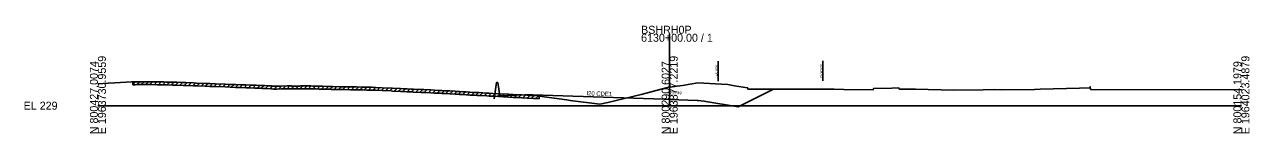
# Model space of a CAD drawing. Extents: x -26 to 1986619, y -10 to 827846.
# Drawn here: x -25.7 to 402.8, y 9990.3 to 10028 of the extents above; entities that cross this region are included whole.
import ezdxf

# ---------------------------------------------------------------- set-up
doc = ezdxf.new("R2010")
doc.units = 0
for name, color, linetype in [('Default', 7, 'Continuous'), ('RD_EX_Road', 7, 'Continuous'), ('RD_PD_ALT2_TrvlWay', 7, 'Continuous'), ('RD_PD_ALT5_LnLine', 7, 'Continuous'), ('RD_PD_ALT5_TrvlWay', 7, 'Continuous'), ('RD_PD_PaveDit', 7, 'Continuous'), ('RD_Sketch2', 7, 'Continuous'), ('RD_XS_ExRW', 7, 'Continuous'), ('RD_XS_NewRW', 7, 'Continuous')]:
    doc.layers.add(name, color=color, linetype=linetype)

msp = doc.modelspace()

# ---------------------------------------------------------------- linework, layer by layer
at = {"layer": 'RD_EX_Road'}
for p, q in [((200, 10000), (200, 10025.2)), ((0, 10000), (200, 10000)), ((200, 10000), (400, 10000))]:
    msp.add_line(p, q, dxfattribs=at)
at = {"layer": 'RD_PD_ALT5_LnLine'}
msp.add_lwpolyline([(0, 10007.66), (3.56, 10007.87), (5.92, 10007.99), (11.81, 10008.3), (12.98, 10008.31), (13.54, 10008.39), (14.2, 10008.4), (15.12, 10008.4), (16.27, 10008.4), (17.1, 10008.39), (17.91, 10008.38), (18.77, 10008.37), (20.83, 10008.33), (22.06, 10008.31), (23.09, 10008.31), (23.91, 10008.29), (26.11, 10008.24), (27.63, 10008.19), (29.76, 10008.11), (30.72, 10008.08), (33.41, 10007.97), (34.44, 10007.93), (37.54, 10007.82), (39.17, 10007.76), (40.78, 10007.7), (41.09, 10007.69), (44.5, 10007.55), (46.23, 10007.47), (48.15, 10007.41), (49.83, 10007.35), (51.76, 10007.29), (53.31, 10007.23), (54.93, 10007.16), (55.4, 10007.14), (56.82, 10007.09), (57.4, 10007.07), (58.21, 10007.05), (59.05, 10007), (60.61, 10006.91), (60.92, 10006.86), (61.42, 10006.84), (62.15, 10006.82), (62.6, 10006.82), (64.06, 10006.85), (66.19, 10006.93), (66.88, 10006.95), (67.6, 10006.9), (67.79, 10006.89), (68.7, 10006.87), (69.54, 10006.86), (70.49, 10006.85), (70.82, 10006.92), (71.13, 10006.92), (72.08, 10006.93), (72.94, 10006.94), (74, 10006.91), (74.47, 10006.9), (75.17, 10006.88), (76.31, 10006.85), (77.41, 10006.83), (78.05, 10006.81), (78.56, 10006.8), (81.06, 10006.74), (81.6, 10006.72), (82.07, 10006.71), (84.73, 10006.64), (85.58, 10006.63), (88.39, 10006.59), (89.1, 10006.58), (90.45, 10006.55), (92.05, 10006.52), (92.6, 10006.51), (93.96, 10006.48), (95.9, 10006.43), (97.2, 10006.38), (99.44, 10006.29), (102.52, 10006.16), (103.09, 10006.13), (105.85, 10006), (106.74, 10005.95), (108.12, 10005.88), (109.62, 10005.81), (110.03, 10005.8), (110.41, 10005.78), (113.1, 10005.66), (114.05, 10005.62), (116.45, 10005.5), (117.71, 10005.44), (119.27, 10005.36), (119.87, 10005.33), (120.26, 10005.31), (121.36, 10005.25), (123.06, 10005.15), (125.02, 10005.04), (125.72, 10005.01), (126.46, 10004.96), (127.65, 10004.88), (128.76, 10004.82), (130.07, 10004.74), (131.82, 10004.65), (132.69, 10004.61), (133.33, 10004.57), (136.05, 10004.42), (136.83, 10004.38), (138.19, 10004.31), (140.12, 10004.21), (143.64, 10003.99), (145.31, 10003.91), (147.14, 10003.81), (148.26, 10003.75), (150.1, 10003.65), (150.69, 10003.62), (152.34, 10003.54), (153.05, 10003.54), (153.64, 10003.54), (154.37, 10003.38), (164.04, 10002.01), (165.18, 10001.87), (175.57, 10000.54), (178.42, 10001.1), (189.98, 10003.92), (199.3, 10006.4), (200, 10006.49), (204.48, 10007.06), (209.89, 10008.02), (218.15, 10007.52), (220.32, 10007.4), (222.69, 10006.9), (227.24, 10006.27), (227.34, 10005.82), (234.38, 10005.8), (244.04, 10005.75), (251.21, 10005.79), (257.55, 10005.76), (260.88, 10005.69), (271.2, 10005.56), (271.3, 10006.01), (277.76, 10006.17), (280.2, 10006.24), (280.3, 10005.79), (285.99, 10005.74), (299.38, 10005.47), (309.62, 10005.58), (313.49, 10005.62), (316.18, 10005.56), (327.63, 10005.68), (329.61, 10005.74), (343.38, 10006.19), (346.96, 10006.25), (347.06, 10006.7), (347.26, 10005.69), (400, 10005.58)], dxfattribs=at)
at = {"layer": 'RD_PD_PaveDit'}
for p, q in [((12.15, 10007.3), (13.18, 10008.34)), ((12.15, 10007.3), (12.15, 10008.3)), ((12.15, 10007.3), (12.98, 10007.31)), ((12.98, 10007.31), (13.54, 10007.39)), ((13.54, 10007.39), (14.2, 10007.4)), ((13.65, 10007.39), (14.66, 10008.4)), ((14.2, 10007.4), (15.12, 10007.4)), ((15.12, 10007.4), (16.27, 10007.4)), ((15.15, 10007.4), (16.14, 10008.4)), ((16.27, 10007.4), (17.1, 10007.39)), ((16.65, 10007.39), (17.64, 10008.38)), ((17.1, 10007.39), (17.91, 10007.38)), ((17.91, 10007.38), (18.77, 10007.37)), ((18.15, 10007.38), (19.13, 10008.36)), ((18.77, 10007.37), (20.83, 10007.33)), ((19.65, 10007.35), (20.63, 10008.33)), ((20.83, 10007.33), (22.06, 10007.31)), ((21.15, 10007.33), (22.13, 10008.31)), ((22.06, 10007.31), (23.09, 10007.31)), ((22.65, 10007.31), (23.63, 10008.3)), ((23.09, 10007.31), (23.91, 10007.29)), ((23.91, 10007.29), (26.11, 10007.24)), ((24.15, 10007.29), (25.12, 10008.26)), ((25.65, 10007.25), (26.62, 10008.22)), ((26.11, 10007.24), (27.63, 10007.19)), ((27.15, 10007.2), (28.11, 10008.17)), ((27.63, 10007.19), (29.76, 10007.11)), ((28.65, 10007.15), (29.61, 10008.12)), ((29.76, 10007.11), (30.72, 10007.08)), ((30.15, 10007.1), (31.11, 10008.06)), ((30.72, 10007.08), (33.41, 10006.97)), ((31.65, 10007.04), (32.61, 10008)), ((33.15, 10006.98), (34.11, 10007.94)), ((33.41, 10006.97), (34.44, 10006.93)), ((34.44, 10006.93), (37.54, 10006.82)), ((34.65, 10006.92), (35.61, 10007.89)), ((36.15, 10006.87), (37.11, 10007.84)), ((37.54, 10006.82), (39.17, 10006.76)), ((37.65, 10006.82), (38.61, 10007.78)), ((39.15, 10006.76), (40.11, 10007.73)), ((39.17, 10006.76), (40.78, 10006.7)), ((40.65, 10006.71), (41.61, 10007.67)), ((40.78, 10006.7), (41.09, 10006.69)), ((41.09, 10006.69), (44.5, 10006.55)), ((42.15, 10006.65), (43.11, 10007.61)), ((43.65, 10006.58), (44.61, 10007.54)), ((44.5, 10006.55), (46.23, 10006.47)), ((45.15, 10006.52), (46.1, 10007.48)), ((46.23, 10006.47), (48.15, 10006.41)), ((46.65, 10006.46), (47.62, 10007.43)), ((48.15, 10006.41), (49.11, 10007.38)), ((48.15, 10006.41), (49.83, 10006.35)), ((49.65, 10006.36), (50.61, 10007.33)), ((49.83, 10006.35), (51.76, 10006.29)), ((51.15, 10006.31), (52.11, 10007.27)), ((51.76, 10006.29), (53.31, 10006.23)), ((52.65, 10006.25), (53.61, 10007.21)), ((54.15, 10006.19), (55.11, 10007.15)), ((55.65, 10006.13), (56.61, 10007.1)), ((57.15, 10006.08), (58.11, 10007.05)), ((58.65, 10006.02), (59.59, 10006.97)), ((60.15, 10005.93), (61.07, 10006.86)), ((61.65, 10005.83), (62.64, 10006.82)), ((63.15, 10005.83), (64.17, 10006.85)), ((64.65, 10005.87), (65.69, 10006.91)), ((66.15, 10005.93), (67.16, 10006.94)), ((67.65, 10005.9), (68.62, 10006.87)), ((69.15, 10005.86), (70.14, 10006.85)), ((70.65, 10005.88), (71.69, 10006.92)), ((72.15, 10005.93), (73.15, 10006.93)), ((73.65, 10005.92), (74.62, 10006.9)), ((75.15, 10005.88), (76.12, 10006.86)), ((76.65, 10005.84), (77.63, 10006.82)), ((78.15, 10005.81), (79.12, 10006.79)), ((79.65, 10005.77), (80.62, 10006.75)), ((81.15, 10005.73), (82.12, 10006.71)), ((82.65, 10005.7), (83.62, 10006.67)), ((84.15, 10005.66), (85.12, 10006.64)), ((85.65, 10005.63), (86.63, 10006.61)), ((87.15, 10005.61), (88.13, 10006.59)), ((88.65, 10005.59), (89.63, 10006.57)), ((90.15, 10005.56), (91.13, 10006.54)), ((91.65, 10005.53), (92.63, 10006.51)), ((93.15, 10005.5), (94.13, 10006.48)), ((94.65, 10005.46), (95.62, 10006.44)), ((96.15, 10005.42), (97.11, 10006.38)), ((97.65, 10005.36), (98.61, 10006.33)), ((99.15, 10005.3), (100.11, 10006.26)), ((53.31, 10006.23), (54.93, 10006.16)), ((54.93, 10006.16), (55.4, 10006.14)), ((55.4, 10006.14), (56.82, 10006.09)), ((56.82, 10006.09), (57.4, 10006.07)), ((57.4, 10006.07), (58.21, 10006.05)), ((58.21, 10006.05), (59.05, 10006)), ((59.05, 10006), (60.61, 10005.91)), ((60.61, 10005.91), (60.92, 10005.86)), ((60.92, 10005.86), (61.42, 10005.84)), ((61.42, 10005.84), (62.15, 10005.82)), ((62.15, 10005.82), (62.6, 10005.82)), ((62.6, 10005.82), (64.06, 10005.85)), ((64.06, 10005.85), (66.19, 10005.93)), ((66.19, 10005.93), (66.88, 10005.95)), ((66.88, 10005.95), (67.6, 10005.9)), ((67.6, 10005.9), (67.79, 10005.89)), ((67.79, 10005.89), (68.7, 10005.87)), ((68.7, 10005.87), (69.54, 10005.86)), ((69.54, 10005.86), (70.49, 10005.85)), ((70.49, 10005.85), (70.82, 10005.92)), ((70.82, 10005.92), (71.13, 10005.92)), ((71.13, 10005.92), (72.08, 10005.93)), ((72.08, 10005.93), (72.94, 10005.94)), ((72.94, 10005.94), (74, 10005.91)), ((74, 10005.91), (74.47, 10005.9)), ((74.47, 10005.9), (75.17, 10005.88)), ((75.17, 10005.88), (76.31, 10005.85)), ((76.31, 10005.85), (77.41, 10005.83)), ((77.41, 10005.83), (78.05, 10005.81)), ((78.05, 10005.81), (78.56, 10005.8)), ((78.56, 10005.8), (81.06, 10005.74)), ((81.06, 10005.74), (81.6, 10005.72)), ((81.6, 10005.72), (82.07, 10005.71)), ((82.07, 10005.71), (84.73, 10005.64)), ((84.73, 10005.64), (85.58, 10005.63)), ((85.58, 10005.63), (88.39, 10005.59)), ((88.39, 10005.59), (89.1, 10005.58)), ((89.1, 10005.58), (90.45, 10005.55)), ((90.45, 10005.55), (92.05, 10005.52)), ((92.05, 10005.52), (92.6, 10005.51)), ((92.6, 10005.51), (93.96, 10005.48)), ((93.96, 10005.48), (95.9, 10005.43)), ((95.9, 10005.43), (97.2, 10005.38)), ((97.2, 10005.38), (99.44, 10005.29)), ((99.44, 10005.29), (102.52, 10005.16)), ((100.65, 10005.24), (101.6, 10006.2)), ((102.15, 10005.18), (103.1, 10006.13)), ((102.52, 10005.16), (103.09, 10005.13)), ((103.09, 10005.13), (105.85, 10005)), ((103.65, 10005.11), (104.6, 10006.06)), ((105.15, 10005.03), (106.1, 10005.99)), ((105.85, 10005), (106.74, 10004.95)), ((106.65, 10004.96), (107.59, 10005.9)), ((106.74, 10004.95), (108.12, 10004.88)), ((108.12, 10004.88), (109.62, 10004.81)), ((108.15, 10004.87), (109.11, 10005.84)), ((109.62, 10004.81), (110.03, 10004.8)), ((109.65, 10004.81), (110.61, 10005.77)), ((110.03, 10004.8), (110.41, 10004.78)), ((110.41, 10004.78), (113.1, 10004.66)), ((111.15, 10004.75), (112.1, 10005.71)), ((112.65, 10004.68), (113.6, 10005.64)), ((113.1, 10004.66), (114.05, 10004.62)), ((114.05, 10004.62), (116.45, 10004.5)), ((114.15, 10004.62), (115.1, 10005.57)), ((115.65, 10004.54), (116.6, 10005.5)), ((116.45, 10004.5), (117.71, 10004.44)), ((117.15, 10004.47), (118.1, 10005.42)), ((117.71, 10004.44), (119.27, 10004.36)), ((118.65, 10004.39), (119.6, 10005.35)), ((119.27, 10004.36), (119.87, 10004.33)), ((119.87, 10004.33), (120.26, 10004.31)), ((120.15, 10004.32), (121.09, 10005.26)), ((120.26, 10004.31), (121.36, 10004.25)), ((121.36, 10004.25), (123.06, 10004.15)), ((121.65, 10004.23), (122.59, 10005.18)), ((123.06, 10004.15), (125.02, 10004.04)), ((123.15, 10004.15), (124.09, 10005.09)), ((124.65, 10004.06), (125.6, 10005.01)), ((125.02, 10004.04), (125.72, 10004.01)), ((125.72, 10004.01), (126.46, 10003.96)), ((126.15, 10003.98), (127.09, 10004.92)), ((126.46, 10003.96), (127.65, 10003.88)), ((127.65, 10003.88), (128.59, 10004.83)), ((127.65, 10003.88), (128.76, 10003.82)), ((128.76, 10003.82), (130.07, 10003.74)), ((129.15, 10003.79), (130.09, 10004.74)), ((130.07, 10003.74), (131.82, 10003.65)), ((130.65, 10003.71), (131.6, 10004.66)), ((131.82, 10003.65), (132.69, 10003.61)), ((132.15, 10003.64), (133.1, 10004.59)), ((132.69, 10003.61), (133.33, 10003.57)), ((133.33, 10003.57), (136.05, 10003.42)), ((133.65, 10003.56), (134.59, 10004.5)), ((135.15, 10003.47), (136.09, 10004.42)), ((136.05, 10003.42), (136.83, 10003.38)), ((136.65, 10003.39), (137.6, 10004.34)), ((136.83, 10003.38), (138.19, 10003.31)), ((138.15, 10003.31), (139.1, 10004.26)), ((138.19, 10003.31), (140.12, 10003.21)), ((139.65, 10003.23), (140.59, 10004.18)), ((140.12, 10003.21), (143.64, 10002.99)), ((141.15, 10003.14), (142.09, 10004.08)), ((142.65, 10003.05), (143.59, 10003.99)), ((143.64, 10002.99), (145.31, 10002.91)), ((144.15, 10002.96), (145.1, 10003.92)), ((145.31, 10002.91), (147.14, 10002.81)), ((145.65, 10002.89), (146.6, 10003.84)), ((147.14, 10002.81), (148.26, 10002.75)), ((147.15, 10002.81), (148.1, 10003.76)), ((148.26, 10002.75), (150.1, 10002.65)), ((148.65, 10002.73), (149.6, 10003.68)), ((150.1, 10002.65), (150.69, 10002.62)), ((150.15, 10002.65), (151.1, 10003.6)), ((150.69, 10002.62), (152.34, 10002.54)), ((151.65, 10002.58), (152.61, 10003.54)), ((152.34, 10002.54), (153.05, 10002.54)), ((153.05, 10002.54), (153.64, 10002.54)), ((153.15, 10002.54), (154.06, 10003.45)), ((153.64, 10002.54), (154.37, 10002.38)), ((154.37, 10003.38), (154.37, 10002.38))]:
    msp.add_line(p, q, dxfattribs=at)
at = {"layer": 'RD_Sketch2'}
msp.add_lwpolyline([(138.62, 10002.41), (139.37, 10008.08), (139.87, 10008.08), (140.62, 10003.41), (149.34, 10003.75), (150.63, 10003.8), (152.14, 10003.75), (162.64, 10003.41), (198.01, 10002.24), (200, 10002.18), (200, 10002.18), (200, 10002.18), (209.66, 10001.78), (209.99, 10001.77), (211.99, 10001.61), (223.97, 9999.6), (230.27, 10002.74), (236.38, 10005.79)], dxfattribs=at)
at = {"layer": 'RD_XS_ExRW'}
msp.add_line((216.95, 10008.59), (216.95, 10015.59), dxfattribs=at)
at = {"layer": 'RD_XS_NewRW'}
msp.add_line((253.56, 10008.74), (253.56, 10015.74), dxfattribs=at)

# ---------------------------------------------------------------- texts
at = {"layer": 'Default'}
msp.add_text('-', height=0.0001, dxfattribs=at).set_placement((0, 10000))
at = {"layer": 'RD_EX_Road'}
for s, p in [('BSHRH0P', (190, 10025.2)), ('6130+00.00 / 1', (190, 10022.4)), ('EL 229', (-26, 9998.6))]:
    msp.add_text(s, height=2.8, dxfattribs=at).set_placement(p)
for s, p in [('N 800427.0074', (0, 9990)), ('E 1963730.9559', (2.8, 9990)), ('N 800290.6027', (200, 9990)), ('E 1963877.2219', (202.8, 9990)), ('N 800154.1979', (400, 9990)), ('E 1964023.4879', (402.8, 9990))]:
    msp.add_text(s, height=2.8, rotation=90, dxfattribs=at).set_placement(p)
at = {"layer": 'RD_PD_ALT2_TrvlWay'}
msp.add_text('I20 CDE1', height=1.5, rotation=358.0852, dxfattribs=at).set_placement((170.87, 10003.63))
at = {"layer": 'RD_PD_ALT5_TrvlWay'}
msp.add_text('235.49', height=1, dxfattribs=at).set_placement((200, 10003.99))
at = {"layer": 'RD_XS_ExRW'}
msp.add_text('EX. R/W ', height=0.75, rotation=90, dxfattribs=at).set_placement((216.69, 10010.26))
at = {"layer": 'RD_XS_NewRW'}
msp.add_text('NEW R/W ', height=0.75, rotation=90, dxfattribs=at).set_placement((253.31, 10009.87))

doc.saveas('drawing.dxf')
